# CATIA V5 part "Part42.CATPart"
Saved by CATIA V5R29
Part number: Top cover
Revision: ANY
Definition: UNKNOWN
Nomenclature: Top cover
Source: Unknown
Bounding box of the stored display mesh (mm): x -2 to 43.99, y 0 to 15, z -24 to 24
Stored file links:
  C:\Users\Administrator\Desktop\프로젝트\Gripper\Part42.CATPart
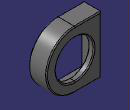
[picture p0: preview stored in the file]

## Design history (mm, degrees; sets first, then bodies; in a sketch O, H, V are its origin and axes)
Body1 "Fillet2" (main body)
  Solid1: solid without history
